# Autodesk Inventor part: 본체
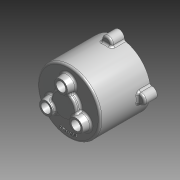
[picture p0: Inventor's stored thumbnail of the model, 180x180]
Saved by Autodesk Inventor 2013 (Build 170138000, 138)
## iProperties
Created: 2021-07
Part Number: 본체
Document SubType Name: 모델링
Designer: mdu
Material: 알루미늄 6061
Density: 1 g/cm^3
변환 표준: STEP AP214IS
파일 이름: C:\Users\SeoGD\Desktop\?쒗뿕\紐몄껜.stp
전처리기: Build: 253, Release: 2010 SP1 - Date: Wed 07/29/2009
전송 단위: 밀리미터
불확실성: 0.01
Author: mdu
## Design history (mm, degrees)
sketch "스케치2"
  geometry: C1 r 50 at (0, 0); 1 further point
  constraints: 1 centre point, 1 coincident
  dimensions: "d9" = 100 diameter of C1
extrude "돌출2" new body sketch "스케치2" distance "d10" = 80; taper "d11" = 0 deg
feature "쉘1" dims "d12" = 5
sketch "스케치3" dims "d13" = 55
  geometry: C1 r 7.5 at (0, 27.5); C2 r 12.5 at (0, 27.5); 2 further points
  constraints: 2 centre point, 2 coincident, 2 vertical alignment, 2 other
  dimensions: "d14" = 15 diameter of C1; "d15" = 25 diameter of C2
extrude "돌출3" join sketch "스케치3" distance "d16" = 12; taper "d17" = -10 deg
sketch "스케치4"
  geometry: L1 (0, 0)-(0, 88); L2 (0, 70)-(14, 70); L3 (-45, 75)-(45, 75) reference; L4 (-50, 80)-(50, 80) reference; L5 (14, 70)-(14, 75); L6 (20, 80)-(20, 88); L7 (20, 88)-(0, 88); L8 (20, 80)-(14, 75)
  constraints: 12 end point, 3 point on line, 2 perpendicular, 1 vertical
  dimensions: "d34" = 40 diameter of L6 L1; "d35" = 90 deg angle of L5 L3; "d36" = 5 distance between parallel lines of L2 L3; "d37" = 8 distance between parallel lines of L7 L4; "d51" = 28 diameter of L5.end L1
revolve "회전1" sketch "스케치4" stored, may be unused: angle "d38" = 90 deg
hole "구멍3" diameter "d41" = 15; stored, may be unused: countersink angle "d45" = 90 deg, drill point angle "d47" = 0 deg; dims "d39" = 10, "d40" = 10, "d42" = 6, "d43" = 22, "d44" = 13, "d46" = 15
chamfer "모따기2" distance "d48" = 1; stored, may be unused: second distance "d49" = 2, angle "d50" = 45 deg
fillet "모깎기4" dims "d78" = 3
hole "구멍2" diameter "d20" = 15; stored, may be unused: countersink angle "d24" = 90 deg, drill point angle "d26" = 118 deg; dims "d21" = 6, "d22" = 25, "d23" = 1, "d25" = 15, "d76" = 10, "d77" = 10
chamfer "모따기1" distance "d27" = 1; stored, may be unused: second distance "d28" = 2, angle "d29" = 45 deg
sketch "스케치9"
  geometry: C1 r 12.5 at (0, 0) reference; C2 r 12.5 at (-23.816, -41.25) reference; C3 r 12.5 at (23.816, -41.25) reference; 1 further point
extrude "돌출5" cut sketch "스케치9" stored distance "d79" = 10; taper "d80" = 0 deg
fillet "모깎기1" dims "d52" = 3
fillet "모깎기2" dims "d53" = 3, "d72" = 0.2
sketch "스케치5"
  geometry: A1 r 50 centre (0, 0) between (50, 0) and (-8.074, 49.344) reference; A2 r 8.5 centre (0, 52) between (8.074, 49.344) and (-8.074, 49.344); 1 further point
  constraints: 5 point on circle, 1 centre point, 1 horizontal alignment
  dimensions: "d54" = 90 deg dimension on point (0, 0) A2.centre A1.start; "d55" = 52 distance of A2.centre point (0, 0); "d56" = 17 diameter of A2
extrude "돌출4" join sketch "스케치5" distance "d57" = 20; taper "d58" = 0 deg
fillet "모깎기3" dims "d59" = 3
hole "구멍4" diameter "d62" = 4.134; stored, may be unused: countersink angle "d66" = 90 deg, drill point angle "d68" = 118 deg; dims "d60" = 10, "d61" = 10, "d63" = 12, "d64" = 22, "d65" = 13, "d67" = 15
sketch "스케치6"
  geometry: C1 r 47 at (0, 0) reference; C2 r 42.5 at (0, 0); 1 further point
  constraints: 1 centre point, 1 coincident, 1 other
  dimensions: "d73" = 85 diameter of C2
feature "엠보싱1" sketch "스케치6" dims "d34" = 40, "d35" = 90 deg, "d36" = 5, "d37" = 8, "d51" = 28, "d74" = 1, "d75" = 0
node "솔리드1"
node "솔리드 본체"
node "곡면 본체"
pattern_circular "원형 패턴1" dims "d31" = 360 deg
pattern_circular "원형 패턴2" dims "d70" = 360 deg
node "솔리드2"
